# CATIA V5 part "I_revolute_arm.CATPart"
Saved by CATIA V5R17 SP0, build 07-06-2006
Part number: I_revolute_arm
Bounding box of the stored display mesh (mm): x -150 to 450, y -50 to 50, z 257.23 to 457.23
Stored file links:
  \\ariel.ad.iei.liu.se\LAB_DELMIA\A1_LAB_INTRO_2011\LAB_INTRO_DATA_2011\I_revolute_arm.CATPart
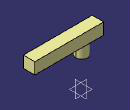
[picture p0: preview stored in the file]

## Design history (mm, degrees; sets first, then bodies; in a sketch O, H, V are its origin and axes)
Body1 (main body)
  Sketch1, origin (-8.5757, 0, 257.2303), H (1, 0, 0), V (0, 1, 0)
    circle A1 centre (0, 0) radius 50
    point P1 (50, 0)
    coincidence: A1 P1, P1 H
  Pad1: profile Sketch1, direction (0, 0, 1), length 100
  Sketch2 on end face of Pad1, origin (0, 0, 357.2303), H (1, 0, 0), V (0, 1, 0)
    line L1 (-150, 50) -> (450, 50)
    line L2 (450, 50) -> (450, -50)
    line L3 (450, -50) -> (-150, -50)
    line L4 (-150, -50) -> (-150, 50)
    horizontal: L1 H, L3 H
    vertical: L2 V, L4 V
  Pad2: profile Sketch2, direction (0, 0, 1), length 100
